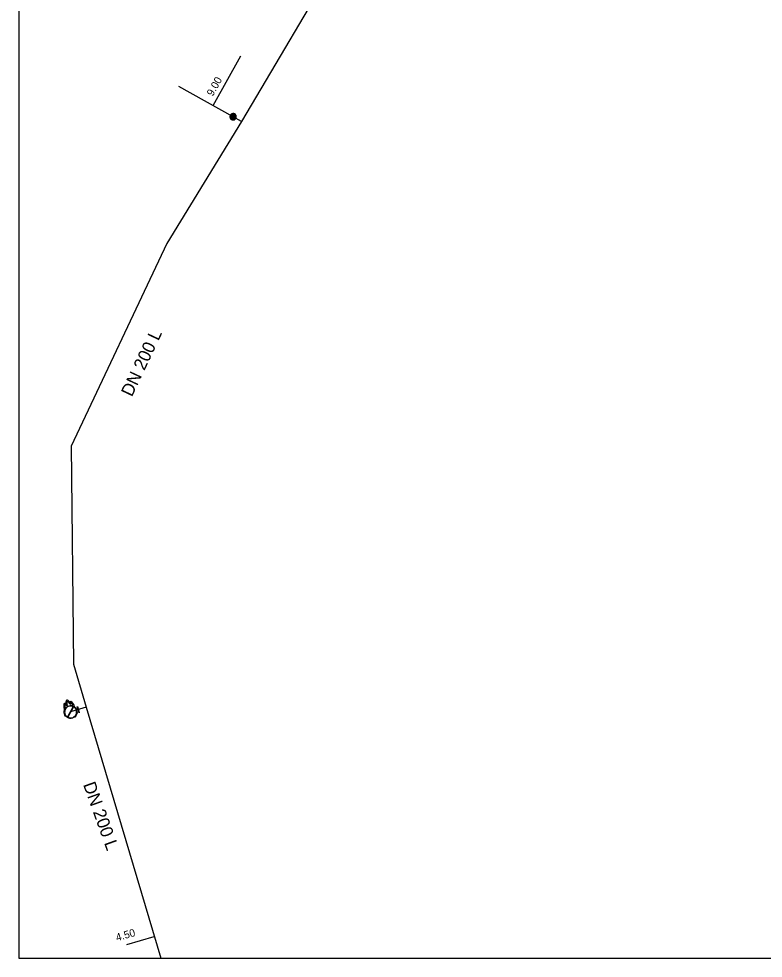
# Model space of a CAD drawing. Extents: x -820257 to -819974, y -1070894 to -1070484.
# Drawn here: x -820256.8 to -820139, y -1070893.9 to -1070745.2 of the extents above; entities that cross this region are included whole.
import ezdxf

# ---------------------------------------------------------------- set-up
doc = ezdxf.new("R2010")
doc.units = 0
for name, color, linetype in [('Default', 7, 'Continuous'), ('Hyd-odbočka', 7, 'Continuous'), ('Hyd-šoupě', 7, 'Continuous'), ('Hydrant', 7, 'Continuous'), ('Oměrka vodovodu', 7, 'Continuous'), ('Oměrka-text', 7, 'Continuous'), ('Přípojka vodovodu', 7, 'Continuous'), ('Přípojkový uzávěr', 7, 'Continuous'), ('Roz-řad', 7, 'Continuous'), ('Roz-řad-popis základní', 7, 'Continuous')]:
    doc.layers.add(name, color=color, linetype=linetype)

msp = doc.modelspace()

# ---------------------------------------------------------------- linework, layer by layer
at = {"layer": 'Default'}
msp.add_line((-820256.81, -1070893.93), (-819975.6, -1070893.93), dxfattribs=at)
msp.add_lwpolyline([(-819975.6, -1070484.4), (-820256.81, -1070484.4), (-820256.81, -1070893.93)], dxfattribs=at)
at = {"layer": 'Hyd-odbočka'}
msp.add_line((-820246.14, -1070854.18), (-820248.61, -1070854.94), dxfattribs=at)
at = {"layer": 'Hyd-šoupě'}
msp.add_lwpolyline([(-820247.53, -1070854.09), (-820247.24, -1070855.04), (-820247.27, -1070855.05), (-820247.56, -1070854.1), (-820247.53, -1070854.09)], dxfattribs=at)
at = {"layer": 'Hydrant'}
for points in [[(-820249.58, -1070853.54), (-820249.51, -1070853.52), (-820249.3, -1070853.73)], [(-820249.17, -1070853.9), (-820249.26, -1070853.93), (-820249.49, -1070853.72)], [(-820249.21, -1070853.04), (-820249.14, -1070853.01)], [(-820248.53, -1070853.43), (-820248.63, -1070853.74), (-820248.7, -1070853.76)], [(-820248.68, -1070853.54), (-820248.62, -1070853.26), (-820248.55, -1070853.24)], [(-820248.19, -1070853.69), (-820248.1, -1070853.88), (-820248.06, -1070853.99)], [(-820249.61, -1070854.32), (-820249.64, -1070854.12)], [(-820249.55, -1070854.59), (-820249.57, -1070854.63)], [(-820249.08, -1070855.75), (-820248.19, -1070854.1)], [(-820248.13, -1070854.13), (-820249.03, -1070855.78)], [(-820248.98, -1070854.01), (-820248.8, -1070853.96)]]:
    msp.add_lwpolyline(points, dxfattribs=at)
for points, degree in [([(-820249.64, -1070854.12), (-820249.67, -1070853.85), (-820249.58, -1070853.54)], 2), ([(-820249.49, -1070853.72), (-820249.61, -1070854.08), (-820249.45, -1070854.41)], 2), ([(-820249.3, -1070853.73), (-820249.34, -1070853.34), (-820249.21, -1070853.04)], 2), ([(-820248.7, -1070853.76), (-820248.83, -1070853.39), (-820249.14, -1070853.15), (-820249.23, -1070853.51), (-820249.17, -1070853.9)], 3), ([(-820249.14, -1070853.01), (-820248.86, -1070853.2), (-820248.68, -1070853.54)], 2), ([(-820248.8, -1070853.96), (-820248.53, -1070853.9), (-820248.19, -1070854.04), (-820248.24, -1070853.7), (-820248.53, -1070853.43)], 3), ([(-820248.55, -1070853.24), (-820248.32, -1070853.45), (-820248.19, -1070853.69)], 2), ([(-820248.01, -1070854.14), (-820247.75, -1070854.33), (-820247.65, -1070854.66), (-820247.53, -1070855.06), (-820247.73, -1070855.42), (-820247.93, -1070855.78), (-820248.32, -1070855.9), (-820248.72, -1070856.02), (-820249.08, -1070855.82), (-820249.45, -1070855.63), (-820249.57, -1070855.23), (-820249.66, -1070854.9), (-820249.55, -1070854.59)], 3), ([(-820249.57, -1070854.63), (-820249.56, -1070854.6), (-820249.55, -1070854.58), (-820249.59, -1070854.43), (-820249.61, -1070854.32)], 3), ([(-820248.19, -1070854.1), (-820248.29, -1070854.05), (-820248.4, -1070854.03), (-820248.65, -1070853.98), (-820248.87, -1070854.04), (-820249.1, -1070854.11), (-820249.28, -1070854.29), (-820249.46, -1070854.47), (-820249.52, -1070854.72), (-820249.58, -1070854.97), (-820249.51, -1070855.21), (-820249.44, -1070855.44), (-820249.25, -1070855.62), (-820249.17, -1070855.7), (-820249.08, -1070855.75)], 3), ([(-820249.45, -1070854.41), (-820249.24, -1070854.11), (-820248.98, -1070854.01)], 2), ([(-820249.03, -1070855.78), (-820248.93, -1070855.83), (-820248.82, -1070855.85), (-820248.57, -1070855.91), (-820248.34, -1070855.84), (-820248.11, -1070855.77), (-820247.93, -1070855.59), (-820247.75, -1070855.41), (-820247.69, -1070855.16), (-820247.64, -1070854.91), (-820247.71, -1070854.67), (-820247.78, -1070854.44), (-820247.96, -1070854.26), (-820248.04, -1070854.18), (-820248.13, -1070854.13)], 3), ([(-820248.06, -1070853.99), (-820248.05, -1070854.02), (-820248.01, -1070854.14)], 2)]:
    msp.add_open_spline(points, degree=degree, dxfattribs=at)
at = {"layer": 'Oměrka vodovodu'}
for p, q in [((-820226.06, -1070758.91), (-820221.66, -1070751.05)), ((-820239.72, -1070891.75), (-820235.36, -1070890.47))]:
    msp.add_line(p, q, dxfattribs=at)
at = {"layer": 'Přípojka vodovodu'}
msp.add_lwpolyline([(-820221.57, -1070761.41), (-820222.88, -1070760.68), (-820231.46, -1070755.88)], dxfattribs=at)
at = {"layer": 'Přípojkový uzávěr'}
for points in [[(-820222.64, -1070760.24), (-820222.53, -1070760.31), (-820222.45, -1070760.42), (-820222.38, -1070760.54), (-820222.38, -1070760.67), (-820222.38, -1070760.81), (-820222.45, -1070760.93), (-820222.51, -1070761.04), (-820222.62, -1070761.11), (-820222.74, -1070761.18), (-820222.88, -1070761.18), (-820223.01, -1070761.18), (-820223.13, -1070761.12), (-820223.24, -1070761.05), (-820223.31, -1070760.94), (-820223.38, -1070760.82), (-820223.38, -1070760.69), (-820223.38, -1070760.55), (-820223.32, -1070760.44), (-820223.25, -1070760.32), (-820223.14, -1070760.25), (-820223.02, -1070760.18), (-820222.88, -1070760.18), (-820222.75, -1070760.18), (-820222.64, -1070760.24)], [(-820222.66, -1070760.29), (-820222.76, -1070760.23), (-820222.88, -1070760.23), (-820223.01, -1070760.23), (-820223.11, -1070760.29), (-820223.22, -1070760.36), (-820223.28, -1070760.46), (-820223.33, -1070760.56), (-820223.34, -1070760.69), (-820223.34, -1070760.81), (-820223.27, -1070760.91), (-820223.21, -1070761.02), (-820223.1, -1070761.08), (-820223, -1070761.13), (-820222.88, -1070761.13), (-820222.75, -1070761.13), (-820222.65, -1070761.07), (-820222.54, -1070761.01), (-820222.49, -1070760.9), (-820222.43, -1070760.8), (-820222.43, -1070760.67), (-820222.43, -1070760.55), (-820222.5, -1070760.44), (-820222.56, -1070760.34), (-820222.66, -1070760.29)], [(-820222.68, -1070760.31), (-820222.58, -1070760.37), (-820222.52, -1070760.46), (-820222.46, -1070760.56), (-820222.46, -1070760.67), (-820222.46, -1070760.79), (-820222.52, -1070760.89), (-820222.57, -1070760.98), (-820222.67, -1070761.04), (-820222.76, -1070761.1), (-820222.88, -1070761.1), (-820222.99, -1070761.1), (-820223.09, -1070761.05), (-820223.18, -1070760.99), (-820223.24, -1070760.9), (-820223.3, -1070760.8), (-820223.3, -1070760.69), (-820223.3, -1070760.57), (-820223.25, -1070760.48), (-820223.19, -1070760.38), (-820223.1, -1070760.32), (-820223, -1070760.26), (-820222.88, -1070760.26), (-820222.77, -1070760.26), (-820222.68, -1070760.31)], [(-820222.7, -1070760.35), (-820222.84, -1070760.28), (-820222.98, -1070760.32), (-820223.13, -1070760.36), (-820223.21, -1070760.5), (-820223.28, -1070760.63), (-820223.24, -1070760.78), (-820223.2, -1070760.93), (-820223.07, -1070761.01), (-820222.93, -1070761.08), (-820222.78, -1070761.04), (-820222.63, -1070761), (-820222.55, -1070760.86), (-820222.48, -1070760.73), (-820222.52, -1070760.58), (-820222.56, -1070760.43), (-820222.7, -1070760.35)], [(-820222.72, -1070760.39), (-820222.6, -1070760.46), (-820222.57, -1070760.59), (-820222.53, -1070760.72), (-820222.6, -1070760.84), (-820222.66, -1070760.96), (-820222.79, -1070761), (-820222.92, -1070761.03), (-820223.04, -1070760.97), (-820223.16, -1070760.9), (-820223.2, -1070760.77), (-820223.23, -1070760.64), (-820223.17, -1070760.52), (-820223.1, -1070760.4), (-820222.97, -1070760.36), (-820222.84, -1070760.33), (-820222.72, -1070760.39)], [(-820222.74, -1070760.43), (-820222.85, -1070760.37), (-820222.96, -1070760.4), (-820223.08, -1070760.43), (-820223.13, -1070760.54), (-820223.19, -1070760.64), (-820223.16, -1070760.76), (-820223.13, -1070760.87), (-820223.02, -1070760.93), (-820222.92, -1070760.99), (-820222.8, -1070760.96), (-820222.69, -1070760.92), (-820222.63, -1070760.82), (-820222.57, -1070760.72), (-820222.6, -1070760.6), (-820222.64, -1070760.49), (-820222.74, -1070760.43)], [(-820222.76, -1070760.46), (-820222.67, -1070760.51), (-820222.64, -1070760.61), (-820222.61, -1070760.71), (-820222.66, -1070760.8), (-820222.71, -1070760.89), (-820222.81, -1070760.92), (-820222.91, -1070760.95), (-820223, -1070760.9), (-820223.09, -1070760.85), (-820223.12, -1070760.75), (-820223.15, -1070760.65), (-820223.1, -1070760.56), (-820223.05, -1070760.47), (-820222.95, -1070760.44), (-820222.85, -1070760.41), (-820222.76, -1070760.46)], [(-820222.78, -1070760.5), (-820222.86, -1070760.46), (-820222.94, -1070760.48), (-820223.02, -1070760.51), (-820223.06, -1070760.58), (-820223.1, -1070760.65), (-820223.08, -1070760.74), (-820223.05, -1070760.82), (-820222.98, -1070760.86), (-820222.91, -1070760.9), (-820222.83, -1070760.88), (-820222.75, -1070760.85), (-820222.7, -1070760.78), (-820222.66, -1070760.71), (-820222.69, -1070760.62), (-820222.71, -1070760.54), (-820222.78, -1070760.5)], [(-820222.8, -1070760.53), (-820222.74, -1070760.57), (-820222.72, -1070760.63), (-820222.7, -1070760.7), (-820222.73, -1070760.76), (-820222.77, -1070760.82), (-820222.84, -1070760.84), (-820222.9, -1070760.86), (-820222.96, -1070760.83), (-820223.03, -1070760.79), (-820223.04, -1070760.73), (-820223.06, -1070760.66), (-820223.03, -1070760.6), (-820222.99, -1070760.54), (-820222.93, -1070760.52), (-820222.86, -1070760.5), (-820222.8, -1070760.53)], [(-820222.82, -1070760.57), (-820222.87, -1070760.55), (-820222.92, -1070760.56), (-820222.97, -1070760.57), (-820222.99, -1070760.62), (-820223.02, -1070760.66), (-820223, -1070760.71), (-820222.99, -1070760.76), (-820222.94, -1070760.79), (-820222.9, -1070760.82), (-820222.85, -1070760.8), (-820222.8, -1070760.79), (-820222.77, -1070760.74), (-820222.75, -1070760.7), (-820222.76, -1070760.65), (-820222.77, -1070760.6), (-820222.82, -1070760.57)], [(-820222.84, -1070760.61), (-820222.81, -1070760.63), (-820222.81, -1070760.66), (-820222.8, -1070760.69), (-820222.81, -1070760.72), (-820222.83, -1070760.75), (-820222.86, -1070760.76), (-820222.89, -1070760.76), (-820222.92, -1070760.75), (-820222.95, -1070760.73), (-820222.96, -1070760.7), (-820222.97, -1070760.67), (-820222.95, -1070760.64), (-820222.93, -1070760.61), (-820222.9, -1070760.61), (-820222.87, -1070760.6), (-820222.84, -1070760.61)], [(-820222.86, -1070760.64), (-820222.88, -1070760.63), (-820222.89, -1070760.64), (-820222.91, -1070760.64), (-820222.92, -1070760.66), (-820222.93, -1070760.67), (-820222.93, -1070760.69), (-820222.92, -1070760.71), (-820222.9, -1070760.72), (-820222.89, -1070760.73), (-820222.87, -1070760.73), (-820222.85, -1070760.72), (-820222.84, -1070760.7), (-820222.83, -1070760.69), (-820222.84, -1070760.67), (-820222.84, -1070760.65), (-820222.86, -1070760.64)]]:
    msp.add_open_spline(points, degree=3, dxfattribs=at)
at = {"layer": 'Roz-řad'}
for points in [[(-820203.65, -1070730.98), (-820205.58, -1070734.34), (-820221.57, -1070761.41), (-820233.36, -1070780.76), (-820248.52, -1070812.85), (-820248.13, -1070847.39), (-820246.14, -1070854.18)], [(-820246.14, -1070854.18), (-820234.34, -1070893.93)]]:
    msp.add_lwpolyline(points, dxfattribs=at)

# ---------------------------------------------------------------- texts
at = {"layer": 'Oměrka-text'}
for s, rotation, p in [(' 9.00', 60.7723, (-820226.32, -1070757.91)), (' 4.50', 16.3319, (-820241.69, -1070891.39))]:
    msp.add_text(s, height=1.2, rotation=rotation, dxfattribs=at).set_placement(p)
at = {"layer": 'Roz-řad-popis základní'}
for rotation, p in [(64.715, (-820238.91, -1070805.14)), (289.7842, (-820246.66, -1070866.42))]:
    msp.add_text('DN 200 L', height=2, rotation=rotation, dxfattribs=at).set_placement(p)

doc.saveas('drawing.dxf')
